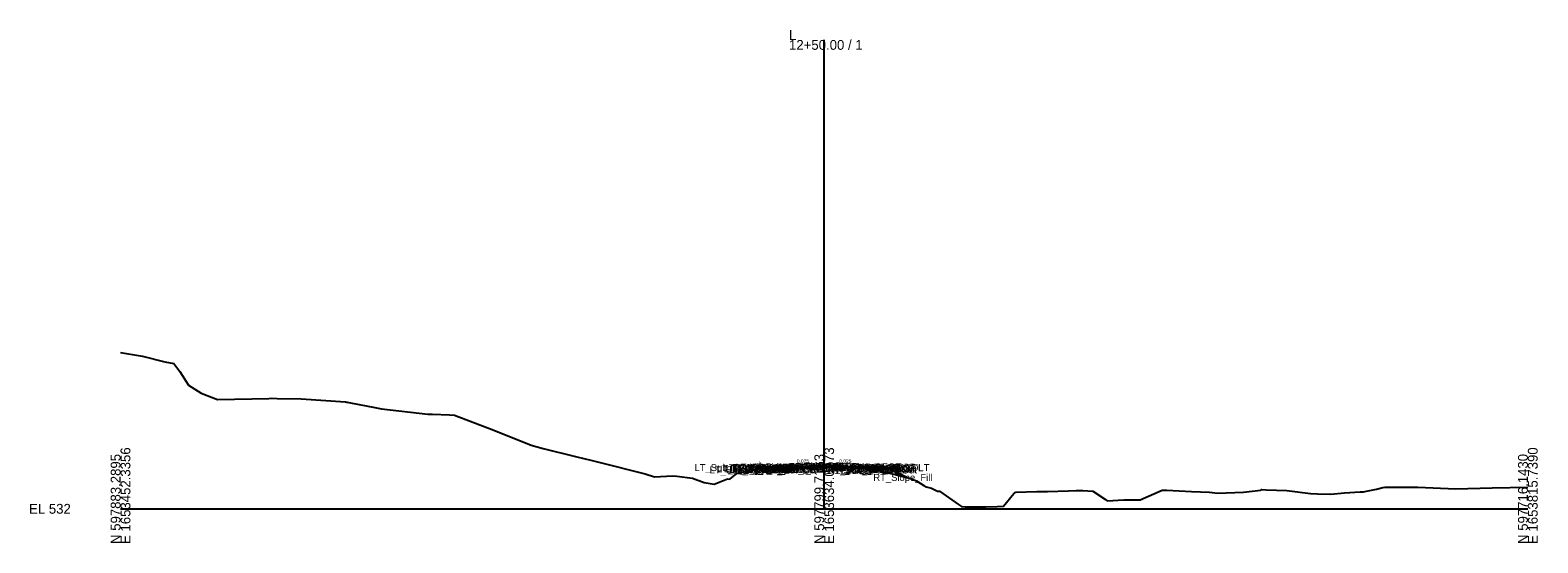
# Model space of a CAD drawing. Extents: x -26 to 403, y -10 to 6021.
# Drawn here: x -25.7 to 402.8, y 990.3 to 1136.2 of the extents above; entities that cross this region are included whole.
import ezdxf

# ---------------------------------------------------------------- set-up
doc = ezdxf.new("R2010")
doc.units = 0
for name, color, linetype in [('Default', 7, 'Continuous'), ('Exist Cross Section Cell', 7, 'Continuous'), ('Exist XS Ground Line', 7, 'Continuous'), ('Prop CMT Pvmt Course 1', 7, 'Continuous'), ('Prop CMT Pvmt Course 1 Wedge', 7, 'Continuous'), ('Prop CMT Pvmt Course 2', 7, 'Continuous'), ('Prop CMT Pvmt Course 2 Wedge', 7, 'Continuous'), ('Prop CMT Pvmt Course 3', 7, 'Continuous'), ('Prop CMT Pvmt Course 3 Wedge', 7, 'Continuous'), ('Prop CMT Pvmt Surface', 7, 'Continuous'), ('Prop CMT Pvmt Surface Shoulder', 7, 'Continuous'), ('Prop CMT Pvmt Wedge Surface 1', 7, 'Continuous'), ('Prop CMT Pvmt Wedge Surface 2', 7, 'Continuous'), ('Prop CMT Pvmt Wedge Surface 3', 7, 'Continuous'), ('Prop CMT Shld Paved Course 1', 7, 'Continuous'), ('Prop CMT Shld Paved Course 2', 7, 'Continuous'), ('Prop CMT Shld Paved Course 3', 7, 'Continuous'), ('Prop CMT Slope Grass', 7, 'Continuous'), ('Prop CMT Subgrade Earthwork', 7, 'Continuous'), ('Prop XS Earthwork Shape', 7, 'Continuous'), ('Prop XS SE Text', 7, 'Continuous'), ('Prop XS Side Slope Text', 7, 'Continuous')]:
    doc.layers.add(name, color=color, linetype=linetype)

msp = doc.modelspace()

# ---------------------------------------------------------------- linework, layer by layer
at = {"layer": 'Exist Cross Section Cell'}
for p, q in [((200, 1000), (200, 1133.4)), ((0, 1000), (200, 1000)), ((200, 1000), (400, 1000))]:
    msp.add_line(p, q, dxfattribs=at)
at = {"layer": 'Exist XS Ground Line'}
msp.add_lwpolyline([(0, 1044.47), (6.26, 1043.4), (12.59, 1041.8), (15.17, 1041.3), (16.83, 1039.07), (19.36, 1035.18), (22.9, 1032.9), (27.59, 1031.06), (42.17, 1031.43), (43.04, 1031.45), (44.52, 1031.38), (51.31, 1031.28), (63.96, 1030.4), (64.24, 1030.38), (64.39, 1030.37), (65.4, 1030.17), (72.31, 1028.83), (74.14, 1028.41), (87.3, 1026.94), (88.71, 1026.97), (93.48, 1026.77), (94.91, 1026.68), (106.1, 1022.33), (116.75, 1018.08), (120.09, 1017.19), (129.34, 1014.89), (134.03, 1013.75), (136.29, 1013.22), (149.16, 1009.96), (151.79, 1009.13), (156.87, 1009.41), (158.08, 1009.31), (162.52, 1008.69), (165.91, 1007.44), (168.68, 1007.04), (172.53, 1008.57), (173.18, 1008.4), (175.21, 1010.02), (181.28, 1011.42), (181.29, 1011.42), (188.05, 1011.28), (194.85, 1011.61), (196.57, 1011.71), (199.68, 1011.88), (200, 1011.87), (201.56, 1011.83), (211.91, 1011.53), (215.23, 1011.02), (215.57, 1010.95), (215.89, 1010.84), (224.57, 1008.65), (226.24, 1007.93), (228.31, 1006.63), (229.02, 1006.29), (230.48, 1005.88), (232.16, 1005.04), (232.81, 1004.98), (238.17, 1001.21), (239.07, 1000.64), (240.07, 1000.58), (245.97, 1000.53), (249.16, 1000.65), (250.99, 1000.74), (253.93, 1004.39), (254.22, 1004.67), (254.46, 1004.69), (260.44, 1004.91), (263.47, 1004.97), (269.48, 1005.12), (271.6, 1005.17), (273.48, 1005.22), (276.33, 1005.02), (280, 1002.61), (280.46, 1002.23), (285.16, 1002.59), (285.85, 1002.52), (289.67, 1002.52), (289.72, 1002.53), (289.85, 1002.59), (296.02, 1005.26), (296.47, 1005.3), (297.39, 1005.29), (304.42, 1004.89), (309.47, 1004.72), (311.75, 1004.49), (319.16, 1004.74), (324.08, 1005.26), (324.42, 1005.45), (325.58, 1005.44), (331.46, 1005.2), (338.19, 1004.4), (340.19, 1004.26), (344, 1004.14), (347.91, 1004.54), (352.36, 1004.82), (353.31, 1004.8), (353.7, 1004.94), (356.96, 1005.56), (358.82, 1006.02), (359.45, 1006.15), (368.52, 1006.14), (368.77, 1006.14), (379.56, 1005.68), (389.83, 1005.94), (400, 1006.19)], dxfattribs=at)
at = {"layer": 'Prop CMT Pvmt Course 1'}
for points in [[(200, 1012.23), (188, 1011.93)], [(188, 1011.93), (188, 1011.73)], [(188, 1011.73), (188.05, 1011.73)], [(188.05, 1011.73), (200, 1012.03)], [(188.05, 1011.73), (188.05, 1011.73)], [(200, 1012.03), (200, 1012.23)], [(200, 1012.23), (212, 1011.93)], [(200, 1012.03), (200, 1012.23)], [(200, 1012.03), (200, 1012.03), (200, 1012.03)], [(211.91, 1011.73), (200, 1012.03)], [(200, 1012.03), (200, 1012.03), (200, 1012.03)], [(212, 1011.73), (211.91, 1011.73)], [(211.91, 1011.73), (211.91, 1011.73)], [(212, 1011.93), (212, 1011.73)]]:
    msp.add_lwpolyline(points, dxfattribs=at)
at = {"layer": 'Prop CMT Pvmt Course 1 Wedge'}
for points in [[(188.05, 1011.73), (194.85, 1011.9), (196.57, 1011.94), (199.68, 1012.02), (200, 1012.03)], [(200, 1011.9), (199.68, 1011.89), (196.57, 1011.81), (194.85, 1011.77), (188.05, 1011.6)], [(188.05, 1011.73), (188.05, 1011.73)], [(188.05, 1011.6), (188.05, 1011.73)], [(188.05, 1011.6), (188.05, 1011.6)], [(200, 1012.03), (200, 1011.9)], [(200, 1012.03), (201.56, 1011.99), (211.91, 1011.73)], [(200, 1011.9), (200, 1012.03)], [(211.91, 1011.6), (201.56, 1011.86), (200, 1011.9)], [(211.91, 1011.73), (211.91, 1011.6)]]:
    msp.add_lwpolyline(points, dxfattribs=at)
at = {"layer": 'Prop CMT Pvmt Course 2'}
for points in [[(188.05, 1011.73), (188, 1011.73)], [(188, 1011.73), (188, 1011.52)], [(188, 1011.52), (188.05, 1011.52)], [(188.05, 1011.52), (188.05, 1011.73)], [(211.91, 1011.52), (211.91, 1011.73)], [(211.91, 1011.73), (212, 1011.73)], [(212, 1011.52), (211.91, 1011.52)], [(212, 1011.73), (212, 1011.52)]]:
    msp.add_lwpolyline(points, dxfattribs=at)
at = {"layer": 'Prop CMT Pvmt Course 2 Wedge'}
for points in [[(188.05, 1011.73), (194.85, 1011.9), (196.57, 1011.94), (199.68, 1012.02), (200, 1012.03)], [(200, 1011.87), (199.68, 1011.88), (197.21, 1011.75), (196.57, 1011.73), (194.85, 1011.69), (188.05, 1011.52)], [(188.05, 1011.73), (188.05, 1011.73)], [(188.05, 1011.52), (188.05, 1011.73)], [(188.05, 1011.52), (188.05, 1011.52)], [(200, 1012.03), (200, 1011.87)], [(200, 1012.03), (201.56, 1011.99), (211.91, 1011.73)], [(200, 1011.87), (200, 1012.03)], [(211.91, 1011.53), (201.56, 1011.83), (200, 1011.87)], [(211.91, 1011.73), (211.91, 1011.53)]]:
    msp.add_lwpolyline(points, dxfattribs=at)
at = {"layer": 'Prop CMT Pvmt Course 3'}
for points in [[(188.05, 1011.52), (188, 1011.52)], [(188, 1011.52), (188, 1011.18)], [(188.05, 1011.19), (188.05, 1011.52)], [(211.91, 1011.52), (212, 1011.52)], [(211.91, 1011.19), (211.91, 1011.52)], [(212, 1011.52), (212, 1011.18)], [(188, 1011.18), (188.05, 1011.19)], [(212, 1011.18), (211.91, 1011.19)]]:
    msp.add_lwpolyline(points, dxfattribs=at)
at = {"layer": 'Prop CMT Pvmt Course 3 Wedge'}
for points in [[(188.05, 1011.52), (194.85, 1011.69), (196.57, 1011.73), (197.21, 1011.75)], [(197.21, 1011.75), (196.57, 1011.71), (194.85, 1011.61), (188.05, 1011.28)], [(188.05, 1011.52), (188.05, 1011.52)], [(188.05, 1011.28), (188.05, 1011.52)], [(188.05, 1011.28), (188.05, 1011.28)]]:
    msp.add_lwpolyline(points, dxfattribs=at)
at = {"layer": 'Prop CMT Pvmt Surface'}
for points in [[(200, 1012.23), (188, 1011.93)], [(200, 1012.23), (212, 1011.93)]]:
    msp.add_lwpolyline(points, dxfattribs=at)
at = {"layer": 'Prop CMT Pvmt Surface Shoulder'}
for points in [[(188, 1011.93), (184, 1011.83)], [(212, 1011.93), (216, 1011.83)]]:
    msp.add_lwpolyline(points, dxfattribs=at)
at = {"layer": 'Prop CMT Pvmt Wedge Surface 1'}
for points in [[(188, 1011.73), (188, 1011.93)], [(188.05, 1011.73), (188, 1011.73)], [(200, 1012.03), (188.05, 1011.73)], [(188.05, 1011.73), (188.05, 1011.73)], [(200, 1012.23), (200, 1012.03), (200, 1012.03), (200, 1012.03)], [(200, 1012.23), (200, 1012.03), (200, 1012.03), (200, 1012.03)], [(200, 1012.03), (211.91, 1011.73)], [(211.91, 1011.73), (211.91, 1011.73)], [(211.91, 1011.73), (212, 1011.73)], [(212, 1011.73), (212, 1011.93)]]:
    msp.add_lwpolyline(points, dxfattribs=at)
at = {"layer": 'Prop CMT Pvmt Wedge Surface 2'}
for points in [[(200, 1012.03), (188, 1011.73)], [(188, 1011.73), (188, 1011.93)], [(200, 1012.23), (200, 1012.03)], [(200, 1012.23), (200, 1012.03)], [(200, 1012.03), (212, 1011.73)], [(212, 1011.73), (212, 1011.93)]]:
    msp.add_lwpolyline(points, dxfattribs=at)
at = {"layer": 'Prop CMT Pvmt Wedge Surface 3'}
for points in [[(188, 1011.52), (188, 1011.93)], [(200, 1011.82), (188, 1011.52)], [(200, 1012.23), (200, 1011.82)], [(200, 1012.23), (200, 1011.82)], [(200, 1011.82), (212, 1011.52)], [(212, 1011.52), (212, 1011.93)]]:
    msp.add_lwpolyline(points, dxfattribs=at)
at = {"layer": 'Prop CMT Shld Paved Course 1'}
for points in [[(188, 1011.93), (184, 1011.83), (183.79, 1011.62)], [(183.79, 1011.62), (188, 1011.73)], [(188, 1011.73), (188, 1011.93)], [(212, 1011.93), (216, 1011.83), (216.21, 1011.62)], [(212, 1011.73), (212, 1011.93)], [(216.21, 1011.62), (212, 1011.73)]]:
    msp.add_lwpolyline(points, dxfattribs=at)
at = {"layer": 'Prop CMT Shld Paved Course 2'}
for points in [[(188, 1011.73), (183.79, 1011.62), (183.57, 1011.41)], [(183.57, 1011.41), (188, 1011.52)], [(188, 1011.52), (188, 1011.73)], [(212, 1011.73), (216.21, 1011.62), (216.43, 1011.41)], [(212, 1011.52), (212, 1011.73)], [(216.43, 1011.41), (212, 1011.52)]]:
    msp.add_lwpolyline(points, dxfattribs=at)
at = {"layer": 'Prop CMT Shld Paved Course 3'}
for points in [[(183.57, 1011.41), (183.23, 1011.06)], [(188, 1011.52), (183.57, 1011.41)], [(183.57, 1011.41), (183.57, 1011.41)], [(188, 1011.18), (188, 1011.52)], [(212, 1011.52), (216.43, 1011.41), (216.43, 1011.41), (216.77, 1011.06)], [(212, 1011.18), (212, 1011.52)], [(183.23, 1011.06), (188, 1011.18)], [(216.77, 1011.06), (212, 1011.18)]]:
    msp.add_lwpolyline(points, dxfattribs=at)
at = {"layer": 'Prop CMT Slope Grass'}
for points in [[(184, 1011.83), (182, 1011.67), (181.49, 1011.42)], [(216, 1011.83), (218, 1011.67), (223.5, 1008.92)]]:
    msp.add_lwpolyline(points, dxfattribs=at)
at = {"layer": 'Prop CMT Subgrade Earthwork'}
for points in [[(183.23, 1011.06), (182.58, 1011.72)], [(211.91, 1011.19), (211.9, 1011.53)], [(216.77, 1011.06), (217.42, 1011.72)], [(188, 1011.18), (183.23, 1011.06)], [(188.05, 1011.19), (188, 1011.18)], [(188.05, 1011.19), (188.07, 1011.28)], [(211.91, 1011.19), (212, 1011.18)], [(212, 1011.18), (216.77, 1011.06)]]:
    msp.add_lwpolyline(points, dxfattribs=at)
at = {"layer": 'Prop XS Earthwork Shape'}
for points in [[(182.91, 1011.39), (182.58, 1011.72), (182, 1011.67), (181.49, 1011.42)], [(182.91, 1011.39), (182.58, 1011.72), (182, 1011.67), (181.49, 1011.42)], [(182.91, 1011.39), (182.58, 1011.72), (182, 1011.67), (181.49, 1011.42)], [(214.58, 1011.12), (216.77, 1011.06), (217.42, 1011.72), (216, 1011.83), (212, 1011.93), (212, 1011.73), (211.91, 1011.73), (200, 1012.03), (188.05, 1011.73), (188, 1011.73), (188, 1011.93), (184, 1011.83), (182.58, 1011.72), (182.91, 1011.39), (188.05, 1011.28), (188.07, 1011.28), (194.85, 1011.61), (196.57, 1011.71), (199.68, 1011.88), (200, 1011.87), (201.56, 1011.83), (211.9, 1011.53), (211.91, 1011.53)], [(214.58, 1011.12), (216.77, 1011.06), (217.42, 1011.72), (216, 1011.83), (212, 1011.93), (212, 1011.73), (211.91, 1011.73), (200, 1012.03), (188.05, 1011.73), (188, 1011.73), (188, 1011.93), (184, 1011.83), (182.58, 1011.72), (182.91, 1011.39), (188.05, 1011.28), (188.07, 1011.28), (194.85, 1011.61), (196.57, 1011.71), (199.68, 1011.88), (200, 1011.87), (201.56, 1011.83), (211.9, 1011.53), (211.91, 1011.53)], [(214.58, 1011.12), (216.77, 1011.06), (217.42, 1011.72), (216, 1011.83), (212, 1011.93), (212, 1011.73), (211.91, 1011.73), (200, 1012.03), (188.05, 1011.73), (188, 1011.73), (188, 1011.93), (184, 1011.83), (182.58, 1011.72), (182.91, 1011.39), (188.05, 1011.28), (188.07, 1011.28), (194.85, 1011.61), (196.57, 1011.71), (199.68, 1011.88), (200, 1011.87), (201.56, 1011.83), (211.9, 1011.53), (211.91, 1011.53)], [(182.91, 1011.39), (188.05, 1011.28), (188.07, 1011.28), (188.05, 1011.19), (188, 1011.18), (183.23, 1011.06)], [(182.91, 1011.39), (188.05, 1011.28), (188.07, 1011.28), (188.05, 1011.19), (188, 1011.18), (183.23, 1011.06)], [(182.91, 1011.39), (188.05, 1011.28), (188.07, 1011.28), (188.05, 1011.19), (188, 1011.18), (183.23, 1011.06)], [(211.9, 1011.53), (211.91, 1011.53), (214.58, 1011.12), (212, 1011.18), (211.91, 1011.19)], [(211.9, 1011.53), (211.91, 1011.53), (214.58, 1011.12), (212, 1011.18), (211.91, 1011.19)], [(211.9, 1011.53), (211.91, 1011.53), (214.58, 1011.12), (212, 1011.18), (211.91, 1011.19)], [(214.58, 1011.12), (215.23, 1011.02), (215.57, 1010.95), (215.89, 1010.84), (223.5, 1008.92), (218, 1011.67), (217.42, 1011.72), (216.77, 1011.06)], [(214.58, 1011.12), (215.23, 1011.02), (215.57, 1010.95), (215.89, 1010.84), (223.5, 1008.92), (218, 1011.67), (217.42, 1011.72), (216.77, 1011.06)], [(214.58, 1011.12), (215.23, 1011.02), (215.57, 1010.95), (215.89, 1010.84), (223.5, 1008.92), (218, 1011.67), (217.42, 1011.72), (216.77, 1011.06)]]:
    msp.add_lwpolyline(points, close=True, dxfattribs=at)

# ---------------------------------------------------------------- texts
at = {"layer": 'Default'}
for s, height, p in [('LT_Sub_Trench_Out_DLT', 2, (163.14, 1010.72)), ('LT_Sub_Trench_Out', 2, (167.44, 1010.06)), ('LT_PS3_Shelf_Out', 2, (169.56, 1010.41)), ('LT_GS_OS_CTL', 2, (171.37, 1010.67)), ('LT_Slope_Fill', 2, (172.01, 1010.42)), ('LT_PV_Sub_Tie_Out', 2, (173.01, 1010.28)), ('LT_PS3_OEOP', 2, (173.81, 1010.41)), ('LT_PS2_OEOP', 2, (174.02, 1010.62)), ('LT_PS1_OEOP', 2, (174.8, 1010.83)), ('LT_PV_OEEOP_EG', 2, (175.6, 1010.28)), ('LT_Sub_OEEOP', 2, (177.27, 1010.19)), ('LT_PV2_OEEOP', 2, (177.36, 1010.73)), ('LT_PV3_OEEOP', 2, (177.36, 1010.52)), ('LT_PV1_OEEOP', 2, (177.93, 1010.73)), ('LT_Sub_OEOT', 2, (178.08, 1010.18)), ('LT_PV2_OEOT', 2, (178.17, 1010.73)), ('LT_PV3_OEOT', 2, (178.17, 1010.52)), ('LT_PV1_OEOT', 2, (178.74, 1010.93)), ('LT_PV_EG_TestPt', 2, (180.44, 1010.57)), ('RT_PV_IEEOP_EG', 2, (188.14, 1010.87)), ('LT_PV_IEEOP_EG', 2, (188.19, 1010.87)), ('RT_PV2_IEEOP', 2, (189.91, 1011.03)), ('RT_PV3_IEEOP', 2, (189.91, 1010.82)), ('LT_PV2_IEEOP', 2, (189.95, 1011.03)), ('LT_PV3_IEEOP', 2, (189.95, 1010.82)), ('RT_PV1_IEEOP', 2, (190.47, 1011.03)), ('LT_PV1_IEEOP', 2, (190.52, 1011.03)), ('RT_PV_EG_TestPt', 2, (192.32, 1010.7)), ('PV2_PGL', 2, (193.91, 1011.03)), ('PV3_PGL', 2, (193.91, 1010.82)), ('PV1_PGL', 2, (194.47, 1011.23)), ('RT_PV_Sub_Tie_Out', 2, (196.79, 1010.53)), ('RT_Sub_Trench_Out_DLT', 2, (197.94, 1010.72)), ('RT_PV_OEEOP_EG', 2, (199.41, 1010.53)), ('RT_Sub_Trench_Out', 2, (200.93, 1010.06)), ('RT_Sub_OEEOP', 2, (201.08, 1010.19)), ('RT_PV2_OEEOP', 2, (201.17, 1010.73)), ('RT_PV3_OEEOP', 2, (201.17, 1010.52)), ('RT_PV1_OEEOP', 2, (201.74, 1010.73)), ('RT_Sub_OEOT', 2, (202.03, 1010.18)), ('RT_PV2_OEOT', 2, (202.13, 1010.73)), ('RT_PV3_OEOT', 2, (202.13, 1010.52)), ('RT_PS3_Shelf_Out', 2, (202.36, 1010.41)), ('RT_PV1_OEOT', 2, (202.69, 1010.93)), ('RT_PS2_OEOP', 2, (206.4, 1010.62)), ('RT_PS3_OEOP', 2, (206.62, 1010.41)), ('RT_PS1_OEOP', 2, (206.76, 1010.83)), ('RT_GS_OS_CTL', 2, (207.32, 1010.67)), ('RT_Slope_Fill', 2, (213.97, 1007.92)), ('-', 0.0001, (0, 1000))]:
    msp.add_text(s, height=height, dxfattribs=at).set_placement(p)
at = {"layer": 'Exist Cross Section Cell'}
for s, p in [('L', (190, 1133.4)), ('12+50.00 / 1', (190, 1130.6)), ('EL 532', (-26, 998.6))]:
    msp.add_text(s, height=2.8, dxfattribs=at).set_placement(p)
for s, p in [('E 1653452.3356', (2.8, 990)), ('E 1653634.0373', (202.8, 990)), ('E 1653815.7390', (402.8, 990)), ('N 597883.2895', (0, 990)), ('N 597799.7163', (200, 990)), ('N 597716.1430', (400, 990))]:
    msp.add_text(s, height=2.8, rotation=90, dxfattribs=at).set_placement(p)
at = {"layer": 'Prop XS SE Text'}
for rotation, p in [(1.4321, (192.24, 1013.04)), (358.5679, (204.29, 1013.13))]:
    msp.add_text('0.025', height=1, rotation=rotation, dxfattribs=at).set_placement(p)
at = {"layer": 'Prop XS Side Slope Text'}
for rotation, p in [(26.5651, (180.7, 1011.86)), (333.4349, (220.38, 1011.32))]:
    msp.add_text('2:1', height=1, rotation=rotation, dxfattribs=at).set_placement(p)

doc.saveas('drawing.dxf')
